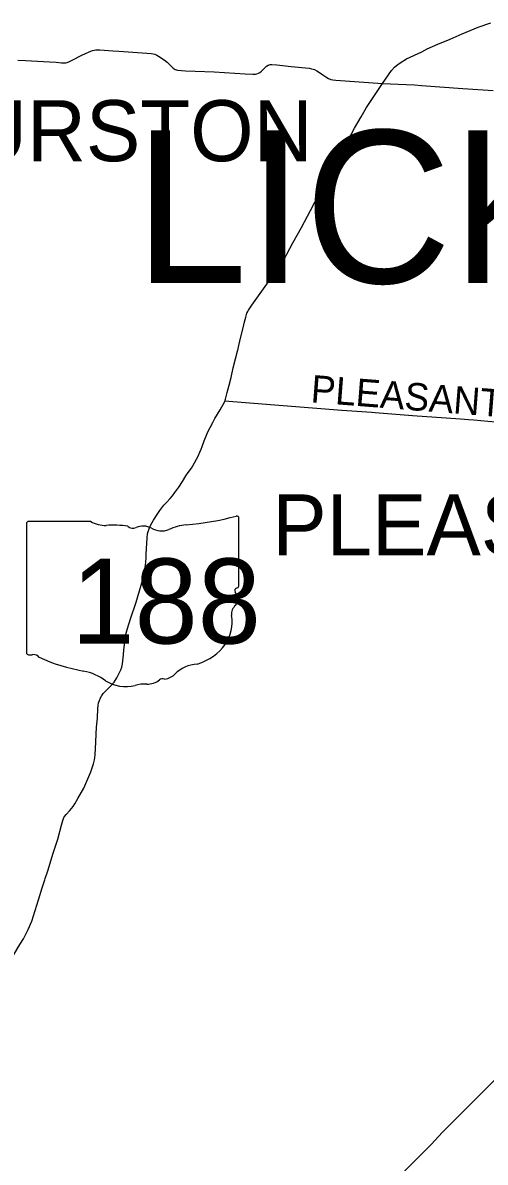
# Model space of a CAD drawing. Extents: x 1761803 to 2441803, y 509895 to 949895.
# Drawn here: x 1955432 to 1970590, y 729125 to 766455 of the extents above; entities that cross this region are included whole.
import ezdxf

# ---------------------------------------------------------------- set-up
doc = ezdxf.new("R2010")
doc.units = 0
for name, color, linetype in [('GM_X_County_Road', 7, 'Continuous'), ('GM_X_Interstate_Location', 7, 'Continuous'), ('GM_X_Minor_Lake', 7, 'Continuous'), ('GM_X_Minor_River_Text', 7, 'Continuous'), ('GM_X_Township_Road', 7, 'Continuous')]:
    doc.layers.add(name, color=color, linetype=linetype)

msp = doc.modelspace()

# ---------------------------------------------------------------- linework, layer by layer
at = {"layer": 'GM_X_County_Road'}
msp.add_lwpolyline([(1962047, 754065), (1965888, 753765), (1966876, 753697), (1966981, 753689), (1968203, 753594), (1969777, 753477), (1970045, 753456), (1970215, 753443), (1970673, 753407), (1975190, 753036), (1975197, 753038)], dxfattribs=at)
at = {"layer": 'GM_X_Minor_Lake'}
for points in [[(1967224, 764465), (1967519, 764895), (1967618, 765002), (1967681, 765057), (1967802, 765140), (1968010, 765270), (1968508, 765507), (1968687, 765598), (1969040, 765750), (1969444, 765923), (1969829, 766094), (1970355, 766306), (1970772, 766455)], [(1956740, 765146), (1956784, 765144), (1956838, 765147), (1956891, 765158), (1956966, 765181), (1957073, 765238), (1957350, 765387), (1957367, 765395)], [(1957367, 765395), (1957486, 765452), (1957586, 765496), (1957661, 765526), (1957719, 765548), (1957773, 765559), (1957830, 765566), (1957954, 765564), (1958389, 765535), (1958585, 765522), (1959499, 765459), (1959635, 765449), (1959706, 765438), (1959763, 765422), (1959823, 765395), (1959886, 765364), (1960071, 765243), (1960162, 765164), (1960238, 765088), (1960364, 764969), (1960427, 764925), (1960468, 764908), (1960505, 764899), (1960767, 764884), (1961077, 764873), (1961707, 764844), (1962718, 764786), (1962977, 764770), (1963055, 764770), (1963109, 764779), (1963158, 764803), (1963198, 764823), (1963260, 764873), (1963376, 764992), (1963424, 765029), (1963472, 765061), (1963503, 765073), (1963537, 765084), (1963600, 765089), (1963761, 765074), (1964227, 765024), (1964820, 764966), (1964901, 764951), (1964948, 764938), (1964999, 764921), (1965070, 764884), (1965128, 764845), (1965265, 764752), (1965364, 764685), (1965453, 764632), (1965524, 764602), (1965600, 764582), (1965696, 764571), (1967224, 764465)], [(1955267, 765233), (1955275, 765232), (1955516, 765216), (1956305, 765173), (1956528, 765161), (1956698, 765148), (1956740, 765146)], [(1962757, 756855), (1962780, 756938), (1962805, 757001), (1962827, 757040), (1962938, 757199), (1963487, 757967), (1963930, 758584), (1963999, 758702), (1964087, 758875), (1964286, 759242), (1964563, 759746), (1964867, 760306), (1965003, 760573), (1965086, 760722), (1965179, 760896), (1965625, 761747), (1965853, 762161), (1966099, 762604), (1966307, 762998), (1966524, 763379), (1966695, 763677), (1967224, 764465)], [(1967224, 764465), (1968004, 764428), (1968272, 764418), (1968505, 764402), (1969853, 764304), (1970847, 764238)], [(1962495, 755781), (1962570, 756126), (1962652, 756456), (1962701, 756654), (1962747, 756814), (1962757, 756855)], [(1962057, 754044), (1962075, 754123), (1962133, 754341), (1962198, 754583), (1962258, 754830), (1962330, 755146), (1962485, 755736), (1962492, 755767), (1962495, 755781)], [(1961576, 753200), (1961657, 753355), (1961726, 753496), (1961900, 753771), (1962057, 754044)], [(1961311, 752573), (1961381, 752760), (1961454, 752944), (1961498, 753052), (1961576, 753200)], [(1961240, 752392), (1961279, 752485), (1961311, 752573)], [(1956249, 738673), (1956427, 739246), (1956579, 739707), (1956698, 740172), (1956740, 740323), (1956779, 740416), (1956815, 740467), (1956851, 740512), (1956970, 740643), (1957082, 740777), (1957139, 740866), (1957239, 741038), (1957430, 741382), (1957658, 741910), (1957748, 742173), (1957784, 742311), (1957795, 742377), (1957807, 742479), (1957819, 742668), (1957848, 743376), (1957876, 743678), (1957891, 743989), (1957900, 744089), (1957919, 744175), (1957949, 744257), (1957984, 744338), (1958022, 744412), (1958072, 744479), (1958133, 744548), (1958188, 744605), (1958280, 744695), (1958422, 744854), (1958513, 744999), (1958557, 745085), (1958651, 745256), (1958678, 745347), (1958696, 745450), (1958735, 745749), (1958746, 745916), (1958775, 746166), (1958804, 746377), (1958867, 746611), (1958958, 746924), (1959146, 747468), (1959316, 748030), (1959366, 748219), (1959429, 748520), (1959470, 748781), (1959481, 748910), (1959481, 749048), (1959507, 749577), (1959522, 749707), (1959542, 749792), (1959573, 749880), (1959631, 750006), (1959719, 750165), (1959832, 750345), (1959923, 750479), (1960059, 750647), (1960147, 750738), (1960266, 750868), (1960344, 750962), (1960420, 751065), (1960544, 751244), (1960667, 751426), (1960778, 751609), (1960856, 751726), (1960958, 751866), (1961007, 751943), (1961183, 752257)], [(1961183, 752257), (1961240, 752392)], [(1954372, 734060), (1954342, 734276), (1954330, 734489), (1954329, 734563), (1954345, 734656), (1954371, 734738), (1954420, 734840), (1954464, 734907), (1954580, 735046), (1954703, 735224), (1954777, 735330), (1955015, 735721), (1955338, 736255), (1955456, 736446), (1955522, 736571), (1955608, 736750), (1955725, 737027), (1955951, 737721), (1956071, 738113), (1956155, 738372), (1956170, 738422)], [(1956170, 738422), (1956249, 738673)]]:
    msp.add_lwpolyline(points, dxfattribs=at)
at = {"layer": 'GM_X_Minor_River_Text'}
msp.add_lwpolyline([(1967929, 728818), (1968829, 729721), (1969179, 730100), (1970475, 731394), (1970959, 731883), (1971297, 732231), (1971614, 732541), (1971690, 732602), (1971765, 732663), (1971835, 732707), (1972070, 732803), (1972441, 732959), (1972744, 733113), (1972971, 733182), (1973431, 733340), (1973746, 733452), (1974142, 733622), (1975020, 733997), (1975387, 734150)], dxfattribs=at)
at = {"layer": 'GM_X_Township_Road'}
for p, q in [((1955557, 750048), (1955557, 745821)), ((1957664, 750121), (1955626, 750121)), ((1962518, 748014), (1962518, 750225)), ((1962518, 748015), (1962518, 748014))]:
    msp.add_line(p, q, dxfattribs=at)
for centre, major_axis, start_param, end_param in [((1955637, 750057), (80.6, 0), 1.712693, 3.28349), ((1958150, 750611), (782, 0), 4.042523, 4.731795), ((1958409, 747748), (2808, 0), 1.404758, 1.657858), ((1959047, 750079), (226, 0), 3.836095, 5.185415), ((1959378, 749590), (469, 0), 0.950623, 2.079405), ((1960980, 748830), (1485, 0), 1.699011, 2.107814), ((1960039, 755883), (7382, 0), 4.814394, 5.042369), ((1962441, 750234), (77.5, 0), 6.141152, 7.989035), ((1959983, 750260), (564, 0), 4.081561, 5.145723), ((1962500, 747852), (120, 0), 1.883978, 3.671073), ((1961737, 747573), (720, 0), 5.934695, 6.695948), ((1962436, 748006), (82.9, 0), 5.05454, 6.418171), ((1962796, 747089), (524, 0), 2.387724, 3.262537), ((1960452, 746808), (1846, 0), 5.101752, 6.440018), ((1955638, 745812), (81.4, 0), 3.00124, 4.508301), ((1955650, 746244), (621, 0), 4.665946, 4.897461), ((1955777, 745577), (224, 0), 0.519207, 1.627899), ((1958604, 749375), (5331, 0), 4.195997, 4.488961), ((1957014, 743922), (1668, 0), 0.823519, 1.323587), ((1959949, 745412), (597, 0), 4.937069, 5.64225), ((1961231, 744635), (1011, 0), 1.647645, 2.488434), ((1958818, 745556), (1058, 0), 4.026481, 4.996735), ((1959430, 744095), (870, 0), 1.495662, 1.94098), ((1959507, 745240), (564, 0), 4.691044, 5.507374), ((1960017, 744831), (159, 0), 1.147584, 2.315152)]:
    msp.add_ellipse(centre, major_axis=major_axis, ratio=0.8, start_param=start_param, end_param=end_param, dxfattribs=at)

# ---------------------------------------------------------------- texts
at = {"layer": 'GM_X_County_Road'}
for s, height, rotation, p in [('THURSTON', 2000, 0, (1950073, 761919)), ('PLEASANTVILLE', 900, 355.5612, (1964852, 754022)), ('PLEASANTVILLE', 2000, 0, (1963608, 749003))]:
    msp.add_text(s, height=height, rotation=rotation, dxfattribs=at).set_placement(p)
at = {"layer": 'GM_X_Interstate_Location'}
msp.add_text('LICKING', height=5000, dxfattribs=at).set_placement((1959081, 757928))
at = {"layer": 'GM_X_Township_Road'}
msp.add_text('188', height=2784.4, dxfattribs=at).set_placement((1957025, 746119))

doc.saveas('drawing.dxf')
